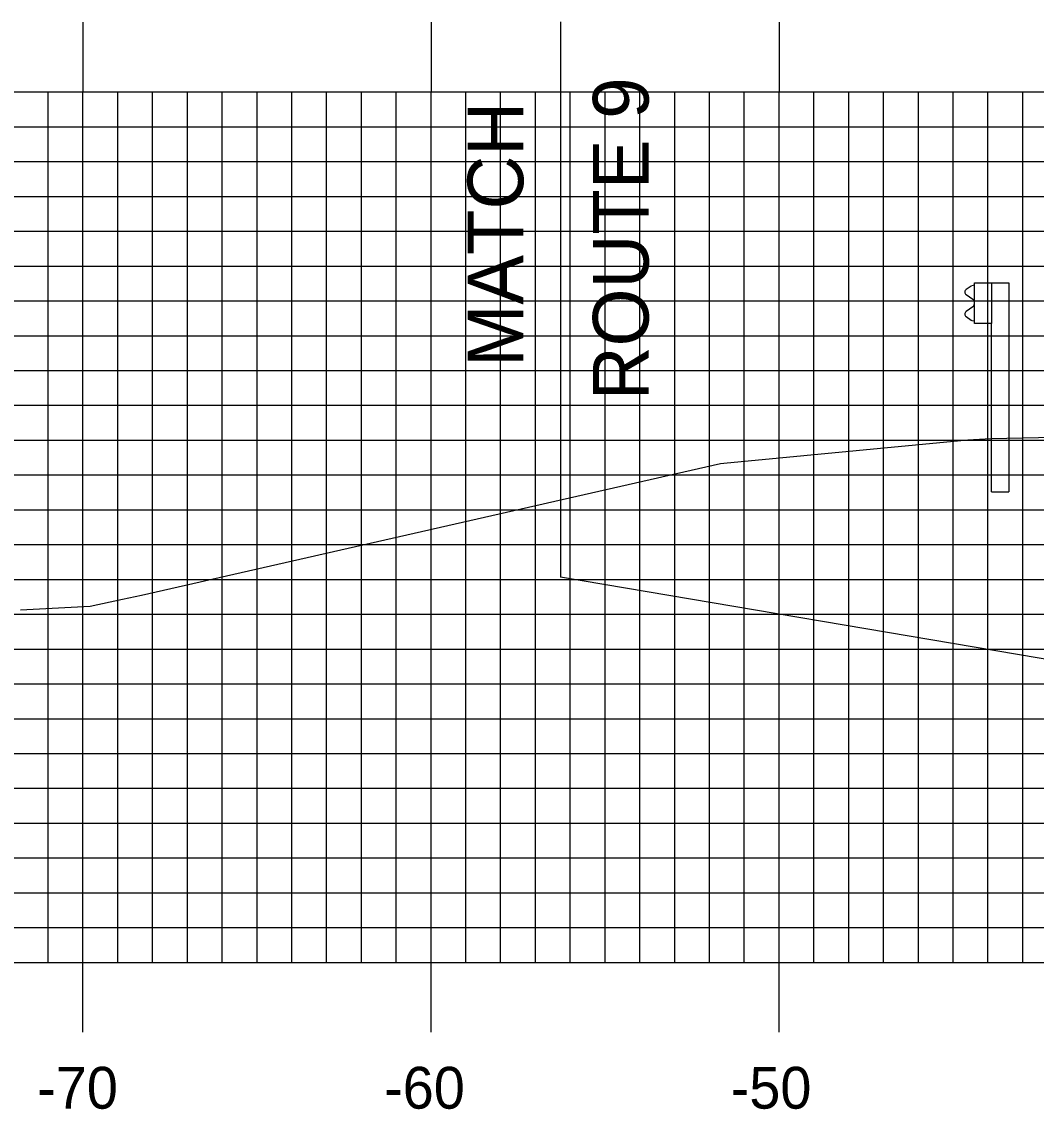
# Model space of a CAD drawing. Extents: x 1685192 to 1685536, y 461260 to 461480.
# Drawn here: x 1685286.47 to 1685315.62, y 461420.99 to 461452.22 of the extents above; entities that cross this region are included whole.
import ezdxf

# ---------------------------------------------------------------- set-up
doc = ezdxf.new("R2010")
doc.units = 0
for name, color, linetype in [('ANNOTATION', 7, 'Continuous'), ('D_Roadway_SlopeLines', 7, 'Continuous'), ('D_Roadway_SubGrade', 7, 'Continuous'), ('H_V ANNOTATION', 7, 'Continuous'), ('M_Guardrail', 7, 'Continuous'), ('MAJOR', 7, 'Continuous'), ('MINOR', 7, 'Continuous'), ('S_Roadway_Centerline', 7, 'Continuous')]:
    doc.layers.add(name, color=color, linetype=linetype)

msp = doc.modelspace()

# ---------------------------------------------------------------- linework, layer by layer
at = {"layer": 'D_Roadway_SlopeLines'}
msp.add_line((1685321.713, 461432.923), (1685301.948, 461436.271), dxfattribs=at)
at = {"layer": 'D_Roadway_SubGrade'}
msp.add_line((1685301.948, 461452.223), (1685301.948, 461436.271), dxfattribs=at)
at = {"layer": 'M_Guardrail'}
for p, q in [((1685313.744, 461444.631), (1685313.601, 461444.531)), ((1685313.843, 461444.653), (1685313.761, 461444.638)), ((1685313.843, 461444.725), (1685314.333, 461444.725)), ((1685313.843, 461443.559), (1685313.843, 461444.725)), ((1685314.333, 461444.725), (1685314.824, 461444.725)), ((1685314.333, 461444.725), (1685314.333, 461443.559)), ((1685314.824, 461444.725), (1685314.824, 461438.725)), ((1685313.601, 461444.388), (1685313.796, 461444.252)), ((1685313.796, 461444.032), (1685313.601, 461443.896)), ((1685313.83, 461444.188), (1685313.83, 461444.097)), ((1685313.601, 461443.753), (1685313.744, 461443.653)), ((1685313.761, 461443.646), (1685313.843, 461443.632)), ((1685314.333, 461443.559), (1685313.843, 461443.559)), ((1685314.333, 461438.725), (1685314.333, 461443.559)), ((1685314.333, 461438.725), (1685314.824, 461438.725))]:
    msp.add_line(p, q, dxfattribs=at)
for centre, major_axis, start_param, end_param in [((1685313.768, 461444.597), (-0.0417, 0), 4.886922, 5.323254), ((1685313.651, 461444.46), (-0.0877, 0), 5.323254, 7.243116), ((1685313.751, 461444.188), (0.0789, 0), 0, 0.959931), ((1685313.751, 461444.097), (0.0789, 0), 5.323254, 6.283185), ((1685313.651, 461443.825), (-0.0877, 0), 5.323254, 7.243116), ((1685313.768, 461443.687), (-0.0417, 0), 0.959931, 1.396263)]:
    msp.add_ellipse(centre, major_axis=major_axis, ratio=0.995501, start_param=start_param, end_param=end_param, dxfattribs=at)
at = {"layer": 'MAJOR'}
for p, q in [((1685288.229, 461452.21), (1685288.229, 461450.206)), ((1685298.229, 461452.21), (1685298.229, 461450.206)), ((1685308.229, 461452.21), (1685308.229, 461450.206)), ((1685218.229, 461450.206), (1685498.229, 461450.206)), ((1685218.229, 461450.206), (1685498.229, 461450.206)), ((1685288.229, 461425.206), (1685288.229, 461450.206)), ((1685298.229, 461425.206), (1685298.229, 461450.206)), ((1685308.229, 461425.206), (1685308.229, 461450.206)), ((1685218.229, 461445.206), (1685498.229, 461445.206)), ((1685218.229, 461440.206), (1685498.229, 461440.206)), ((1685218.229, 461435.206), (1685498.229, 461435.206)), ((1685218.229, 461430.206), (1685498.229, 461430.206)), ((1685218.229, 461425.206), (1685498.229, 461425.206)), ((1685218.229, 461425.206), (1685498.229, 461425.206)), ((1685288.229, 461423.202), (1685288.229, 461425.206)), ((1685298.229, 461423.202), (1685298.229, 461425.206)), ((1685308.229, 461423.202), (1685308.229, 461425.206))]:
    msp.add_line(p, q, dxfattribs=at)
at = {"layer": 'MINOR'}
for p, q in [((1685287.229, 461425.206), (1685287.229, 461450.206)), ((1685289.229, 461425.206), (1685289.229, 461450.206)), ((1685290.229, 461425.206), (1685290.229, 461450.206)), ((1685291.229, 461425.206), (1685291.229, 461450.206)), ((1685292.229, 461425.206), (1685292.229, 461450.206)), ((1685293.229, 461425.206), (1685293.229, 461450.206)), ((1685294.229, 461425.206), (1685294.229, 461450.206)), ((1685295.229, 461425.206), (1685295.229, 461450.206)), ((1685296.229, 461425.206), (1685296.229, 461450.206)), ((1685297.229, 461425.206), (1685297.229, 461450.206)), ((1685299.229, 461425.206), (1685299.229, 461450.206)), ((1685300.229, 461425.206), (1685300.229, 461450.206)), ((1685301.229, 461425.206), (1685301.229, 461450.206)), ((1685302.229, 461425.206), (1685302.229, 461450.206)), ((1685303.229, 461425.206), (1685303.229, 461450.206)), ((1685304.229, 461425.206), (1685304.229, 461450.206)), ((1685305.229, 461425.206), (1685305.229, 461450.206)), ((1685306.229, 461425.206), (1685306.229, 461450.206)), ((1685307.229, 461425.206), (1685307.229, 461450.206)), ((1685309.229, 461425.206), (1685309.229, 461450.206)), ((1685310.229, 461425.206), (1685310.229, 461450.206)), ((1685311.229, 461425.206), (1685311.229, 461450.206)), ((1685312.229, 461425.206), (1685312.229, 461450.206)), ((1685313.229, 461425.206), (1685313.229, 461450.206)), ((1685314.229, 461425.206), (1685314.229, 461450.206)), ((1685315.229, 461425.206), (1685315.229, 461450.206)), ((1685218.229, 461449.206), (1685498.229, 461449.206)), ((1685218.229, 461448.206), (1685498.229, 461448.206)), ((1685218.229, 461447.206), (1685498.229, 461447.206)), ((1685218.229, 461446.206), (1685498.229, 461446.206)), ((1685218.229, 461444.206), (1685498.229, 461444.206)), ((1685218.229, 461443.206), (1685498.229, 461443.206)), ((1685218.229, 461442.206), (1685498.229, 461442.206)), ((1685218.229, 461441.206), (1685498.229, 461441.206)), ((1685218.229, 461439.206), (1685498.229, 461439.206)), ((1685218.229, 461438.206), (1685498.229, 461438.206)), ((1685218.229, 461437.206), (1685498.229, 461437.206)), ((1685218.229, 461436.206), (1685498.229, 461436.206)), ((1685218.229, 461434.206), (1685498.229, 461434.206)), ((1685218.229, 461433.206), (1685498.229, 461433.206)), ((1685218.229, 461432.206), (1685498.229, 461432.206)), ((1685218.229, 461431.206), (1685498.229, 461431.206)), ((1685218.229, 461429.206), (1685498.229, 461429.206)), ((1685218.229, 461428.206), (1685498.229, 461428.206)), ((1685218.229, 461427.206), (1685498.229, 461427.206)), ((1685218.229, 461426.206), (1685498.229, 461426.206))]:
    msp.add_line(p, q, dxfattribs=at)
at = {"layer": 'S_Roadway_Centerline'}
msp.add_lwpolyline([(1685286.43, 461435.332), (1685288.431, 461435.437), (1685289.361, 461435.639), (1685289.912, 461435.758), (1685306.542, 461439.532), (1685306.637, 461439.548), (1685308.936, 461439.765), (1685313.647, 461440.214), (1685314.316, 461440.255), (1685330.697, 461440.593), (1685332.454, 461440.571), (1685336.875, 461440.432), (1685338.988, 461440.38), (1685348.379, 461439.9), (1685358.138, 461440.263), (1685360.692, 461440.305), (1685367.617, 461440.119), (1685369.76, 461440.052), (1685370.232, 461439.98), (1685380.088, 461439.409), (1685388.173, 461438.92)], dxfattribs=at)

# ---------------------------------------------------------------- texts
at = {"layer": 'ANNOTATION'}
for s, p in [('ROUTE 9', (1685304.479, 461441.352)), ('MATCH', (1685300.879, 461442.314))]:
    msp.add_text(s, height=1.6, rotation=90, dxfattribs=at).set_placement(p)
at = {"layer": 'H_V ANNOTATION'}
for s, p in [('-70', (1685286.913, 461421.006)), ('-60', (1685296.881, 461421.006)), ('-50', (1685306.838, 461421.006))]:
    msp.add_text(s, height=1.2, dxfattribs=at).set_placement(p)

doc.saveas('drawing.dxf')
